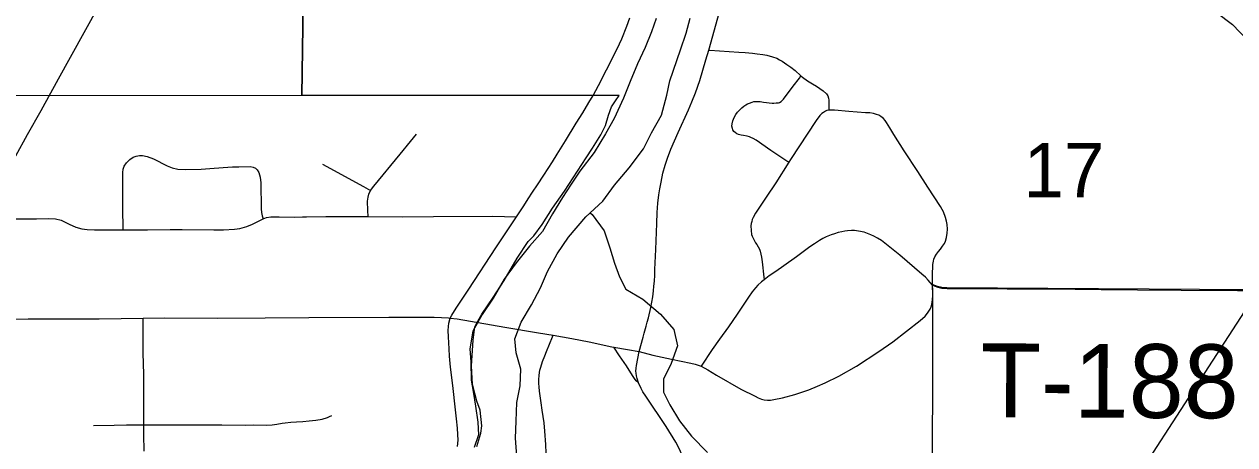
# Model space of a CAD drawing. Extents: x 0 to 34, y 0 to 22.
# Drawn here: x 4.151 to 4.6165, y 16.4424 to 16.6042 of the extents above; entities that cross this region are included whole.
import ezdxf

# ---------------------------------------------------------------- set-up
doc = ezdxf.new("R2010")
doc.units = 0
for name, color, linetype in [('GM_X_City_Street', 7, 'Continuous'), ('GM_X_Corporation', 7, 'Continuous'), ('GM_X_Major_River', 7, 'Continuous'), ('GM_X_Minor_River', 7, 'Continuous'), ('GM_X_Rail_Line', 7, 'Continuous'), ('GM_X_Section_Text', 7, 'Continuous'), ('GM_X_State_Route', 7, 'Continuous'), ('GM_X_Township_Road', 7, 'Continuous'), ('GM_X_Township_Road_Text', 7, 'Continuous')]:
    doc.layers.add(name, color=color, linetype=linetype)

msp = doc.modelspace()

# ---------------------------------------------------------------- linework, layer by layer
at = {"layer": 'GM_X_City_Street'}
for points in [[(4.31768, 16.44178), (4.31786, 16.44419), (4.3178, 16.44636), (4.31761, 16.44884), (4.31728, 16.45232), (4.31681, 16.45588), (4.31578, 16.46515), (4.31494, 16.47224), (4.31456, 16.47645), (4.31439, 16.47932), (4.31411, 16.48398), (4.31407, 16.48635), (4.31419, 16.48793), (4.31435, 16.48913), (4.31478, 16.49112), (4.31549, 16.49227), (4.31717, 16.495), (4.322, 16.50227), (4.33243, 16.51819), (4.34034, 16.53016), (4.34313, 16.53439), (4.34479, 16.537), (4.34649, 16.53959), (4.34837, 16.54244), (4.35077, 16.54608), (4.35412, 16.55131), (4.35591, 16.5542), (4.35909, 16.5594), (4.36331, 16.56621), (4.36578, 16.57013), (4.36818, 16.57412), (4.36973, 16.5768), (4.37181, 16.58061), (4.37497, 16.58665), (4.37898, 16.5947), (4.38078, 16.59862), (4.38278, 16.60347), (4.38391, 16.60667)], [(4.38744, 16.47824), (4.38899, 16.48386), (4.38941, 16.48534), (4.39014, 16.48802), (4.39051, 16.48953), (4.39101, 16.4913), (4.39193, 16.4952), (4.39272, 16.49935), (4.39305, 16.50157), (4.39313, 16.50338), (4.39338, 16.50535), (4.39347, 16.50765), (4.39355, 16.50982), (4.39387, 16.51756), (4.39421, 16.52751), (4.39444, 16.53183), (4.39469, 16.53537), (4.3951, 16.53858), (4.39543, 16.54088), (4.39592, 16.54351), (4.39658, 16.54688), (4.39748, 16.54993), (4.39839, 16.55272), (4.3997, 16.55618), (4.40242, 16.56251), (4.4064, 16.57129), (4.40776, 16.57435), (4.40913, 16.57786), (4.41076, 16.58254), (4.41195, 16.58652), (4.41317, 16.59056), (4.41422, 16.59427)], [(4.41422, 16.59427), (4.41468, 16.59424), (4.42576, 16.59344), (4.42824, 16.5933), (4.43103, 16.59304), (4.43289, 16.59287), (4.43506, 16.59257), (4.4366, 16.59229), (4.43874, 16.59171), (4.44036, 16.59112), (4.44144, 16.59058), (4.44248, 16.59003), (4.44425, 16.58876), (4.44579, 16.58767), (4.4474, 16.58642), (4.44968, 16.58431)], [(4.44498, 16.55109), (4.4442, 16.55159), (4.43817, 16.55565), (4.43242, 16.55955), (4.43131, 16.56022), (4.43044, 16.56062), (4.42985, 16.56084), (4.42904, 16.56109), (4.42765, 16.5614), (4.42671, 16.56155), (4.42568, 16.56182), (4.42497, 16.56211), (4.42438, 16.56251), (4.42391, 16.563), (4.42354, 16.56357), (4.42334, 16.56409), (4.42316, 16.56499), (4.4232, 16.56589), (4.42345, 16.56702), (4.42398, 16.56832), (4.42466, 16.56953), (4.42535, 16.57043), (4.426, 16.57118), (4.42696, 16.57205), (4.4277, 16.57267), (4.42851, 16.5732), (4.42919, 16.57358), (4.42988, 16.57391), (4.4309, 16.57429), (4.43162, 16.57444), (4.43239, 16.5745), (4.43317, 16.5745), (4.43401, 16.57444), (4.43534, 16.57426), (4.43647, 16.57411), (4.43749, 16.57398), (4.43865, 16.57387), (4.43932, 16.57385), (4.44022, 16.57392), (4.441, 16.57401), (4.44149, 16.57417), (4.44208, 16.57451), (4.44252, 16.57489), (4.44295, 16.57544), (4.44664, 16.58035), (4.44907, 16.58351), (4.44968, 16.58431)], [(4.44968, 16.58431), (4.45022, 16.58387), (4.45225, 16.58247), (4.4541, 16.58134), (4.45564, 16.58038), (4.45826, 16.57857), (4.45945, 16.57746), (4.46005, 16.57665), (4.46028, 16.57583), (4.4604, 16.57497), (4.46039, 16.57402), (4.46036, 16.57193), (4.46035, 16.5711)], [(4.46035, 16.5711), (4.4597, 16.57098), (4.45913, 16.57073), (4.45834, 16.57032), (4.45773, 16.56987), (4.45696, 16.56909), (4.45556, 16.56713), (4.44564, 16.55213), (4.44498, 16.55109)], [(4.50031, 16.50375), (4.50025, 16.50865), (4.50036, 16.51055), (4.50043, 16.51174), (4.50063, 16.51301), (4.5008, 16.51387), (4.50117, 16.51478), (4.50182, 16.51577), (4.50256, 16.51671), (4.50334, 16.5177), (4.50417, 16.51877), (4.50483, 16.51984), (4.50528, 16.52078), (4.50565, 16.52214), (4.50589, 16.52383), (4.50602, 16.52539), (4.50585, 16.5272), (4.50562, 16.52848), (4.50525, 16.52991), (4.50445, 16.53197), (4.50396, 16.53296), (4.5033, 16.53407), (4.49853, 16.54147), (4.49457, 16.5476), (4.48942, 16.55556), (4.48545, 16.56176), (4.48388, 16.56439), (4.48255, 16.56638), (4.48207, 16.56716), (4.48137, 16.56798), (4.4804, 16.56878), (4.47966, 16.5692), (4.4787, 16.56955), (4.47759, 16.56987), (4.47619, 16.57008), (4.47447, 16.57016), (4.4681, 16.57062), (4.46262, 16.5711), (4.46121, 16.57118), (4.46035, 16.5711)], [(4.28423, 16.5402), (4.28552, 16.54196), (4.29559, 16.55421), (4.2995, 16.55904), (4.3019, 16.56189)], [(4.18908, 16.52511), (4.18906, 16.52647), (4.18898, 16.53226), (4.18895, 16.54717), (4.18906, 16.5484), (4.1895, 16.54956), (4.19033, 16.55084), (4.19166, 16.55214), (4.19296, 16.55301), (4.19409, 16.5535), (4.1953, 16.55373), (4.19654, 16.5537), (4.19835, 16.55328), (4.20068, 16.55241), (4.20595, 16.54975), (4.20796, 16.54893), (4.21008, 16.54848), (4.21285, 16.54829), (4.21905, 16.54841), (4.22402, 16.54883), (4.22927, 16.5492), (4.2311, 16.54933), (4.23358, 16.54941), (4.23791, 16.54951), (4.23912, 16.54928), (4.23994, 16.54887), (4.24059, 16.54823), (4.24121, 16.54716), (4.24176, 16.54536), (4.24203, 16.5432), (4.24215, 16.53325), (4.24225, 16.53184), (4.24252, 16.53055), (4.24286, 16.52935)], [(4.26573, 16.55036), (4.28144, 16.54173), (4.28423, 16.5402)], [(4.44498, 16.55109), (4.44, 16.54322), (4.43632, 16.53767), (4.43377, 16.53381), (4.4322, 16.53146), (4.4313, 16.52989), (4.43093, 16.52903), (4.43076, 16.52834), (4.43056, 16.52755), (4.43047, 16.52659), (4.43049, 16.5248), (4.43068, 16.52333), (4.43089, 16.52261), (4.43151, 16.52134), (4.43225, 16.52015), (4.43274, 16.51941), (4.43328, 16.51859), (4.43373, 16.51772), (4.43397, 16.51686), (4.43426, 16.51579), (4.43447, 16.5146), (4.43472, 16.51283), (4.43538, 16.50695), (4.43549, 16.5059)], [(4.2833, 16.53026), (4.28321, 16.53257), (4.28308, 16.5361), (4.28322, 16.53765), (4.28353, 16.53885), (4.28423, 16.5402)], [(4.1446, 16.52931), (4.15577, 16.5294), (4.16048, 16.52951), (4.16302, 16.52929), (4.16524, 16.5288), (4.16834, 16.52729), (4.17086, 16.52619), (4.17318, 16.52554), (4.17527, 16.52522), (4.17802, 16.52509), (4.18908, 16.52511), (4.19011, 16.52512), (4.19848, 16.52517), (4.20716, 16.52521), (4.21181, 16.52518), (4.22389, 16.52514), (4.22759, 16.52517), (4.23189, 16.52532), (4.23398, 16.52563), (4.23661, 16.52634), (4.23886, 16.52724), (4.24286, 16.52935), (4.24421, 16.52981), (4.24585, 16.53005), (4.24901, 16.53012), (4.2549, 16.52999), (4.25799, 16.53005), (4.25955, 16.53009), (4.26699, 16.53024), (4.27632, 16.53023), (4.27911, 16.53023), (4.2833, 16.53026), (4.29629, 16.53014), (4.3084, 16.53027), (4.33108, 16.53042), (4.34034, 16.53016)], [(4.50031, 16.50375), (4.49863, 16.5058), (4.49763, 16.50688), (4.49623, 16.50809), (4.48775, 16.51537), (4.48193, 16.52003), (4.48065, 16.52094), (4.4791, 16.52194), (4.47772, 16.52267), (4.47662, 16.52322), (4.47534, 16.52374), (4.474, 16.52418), (4.47187, 16.52464), (4.47028, 16.5248), (4.46909, 16.52482), (4.46757, 16.52472), (4.46658, 16.52456), (4.46543, 16.52435), (4.46394, 16.52403), (4.46259, 16.52358), (4.46128, 16.52312), (4.45943, 16.52237), (4.45811, 16.52174), (4.45677, 16.52095), (4.4549, 16.51974), (4.4531, 16.51851), (4.44796, 16.51478), (4.44311, 16.51123), (4.43998, 16.50913), (4.43743, 16.50736), (4.43549, 16.5059)], [(4.43549, 16.5059), (4.43447, 16.50514), (4.43316, 16.50386), (4.43217, 16.50284), (4.43098, 16.50127), (4.42954, 16.49918), (4.42723, 16.49579), (4.42521, 16.49266), (4.42187, 16.4878), (4.41836, 16.48297), (4.41553, 16.47908), (4.41131, 16.47268)], [(4.41131, 16.47268), (4.41393, 16.47119), (4.41717, 16.46913), (4.4266, 16.46383), (4.43209, 16.46104), (4.43328, 16.46046), (4.43447, 16.45999), (4.43556, 16.45975), (4.43682, 16.45958), (4.43804, 16.45958), (4.4392, 16.45976), (4.44256, 16.4604), (4.44736, 16.46174), (4.44969, 16.46251), (4.45266, 16.46357), (4.45607, 16.46499), (4.45896, 16.46624), (4.46425, 16.46885), (4.471, 16.47269), (4.47961, 16.47828), (4.48497, 16.48201), (4.49555, 16.49021), (4.49742, 16.49186), (4.49841, 16.49304), (4.49891, 16.49383), (4.49937, 16.49464), (4.49973, 16.49546), (4.49999, 16.49639), (4.50013, 16.49726), (4.50028, 16.49823), (4.50041, 16.5), (4.50031, 16.50375)], [(4.11255, 16.49088), (4.12422, 16.49068), (4.15248, 16.49082), (4.1798, 16.4909), (4.1968, 16.49115)], [(4.19709, 16.4399), (4.19705, 16.44641), (4.19703, 16.45012), (4.19704, 16.45215), (4.19705, 16.45855), (4.19701, 16.46415), (4.19699, 16.46942), (4.19676, 16.47781), (4.19682, 16.48371), (4.19681, 16.48903), (4.1968, 16.49115)], [(4.1968, 16.49115), (4.20495, 16.49127), (4.22543, 16.49115), (4.24372, 16.49122), (4.26042, 16.49131), (4.29123, 16.49149), (4.3086, 16.49152), (4.31148, 16.4914), (4.31414, 16.4912), (4.31478, 16.49112)], [(4.31478, 16.49112), (4.31751, 16.4908), (4.33588, 16.48764), (4.34875, 16.48551), (4.35441, 16.48451)], [(4.35174, 16.43912), (4.35158, 16.44253), (4.35121, 16.44769), (4.35099, 16.45078), (4.35013, 16.45577), (4.34976, 16.45855), (4.34939, 16.46126), (4.34914, 16.46299), (4.34901, 16.46471), (4.34893, 16.46598), (4.34895, 16.46743), (4.34901, 16.46922), (4.34932, 16.47107), (4.34963, 16.47224), (4.35031, 16.47446), (4.35117, 16.47656), (4.35191, 16.47835), (4.35419, 16.48396), (4.35441, 16.48451)], [(4.35441, 16.48451), (4.36157, 16.48324), (4.36823, 16.48195), (4.37691, 16.48012), (4.37773, 16.47996)], [(4.37773, 16.47996), (4.38305, 16.47902), (4.38744, 16.47824)], [(4.38727, 16.46629), (4.38639, 16.46705), (4.38571, 16.46785), (4.3849, 16.46909), (4.38256, 16.47273), (4.37997, 16.4766), (4.37773, 16.47996)], [(4.38727, 16.46629), (4.38675, 16.46793), (4.38647, 16.46897), (4.38627, 16.46989), (4.38624, 16.47068), (4.38632, 16.47193), (4.38643, 16.47286), (4.38744, 16.47824)], [(4.38744, 16.47824), (4.39268, 16.47687), (4.39985, 16.47536), (4.40735, 16.47386), (4.409, 16.47346), (4.41131, 16.47268)], [(4.4054, 16.36954), (4.40567, 16.37964), (4.40607, 16.39475), (4.40636, 16.41465), (4.40625, 16.42644), (4.40607, 16.42857), (4.40595, 16.43043), (4.40559, 16.43262), (4.40532, 16.43405), (4.40484, 16.43567), (4.40449, 16.437), (4.40404, 16.43823), (4.40337, 16.43984), (4.40265, 16.44143), (4.40154, 16.4434), (4.3978, 16.44946), (4.39002, 16.46111), (4.38895, 16.46277), (4.38824, 16.46407), (4.38727, 16.46629)], [(4.17762, 16.44977), (4.18567, 16.44998), (4.19032, 16.45008), (4.19703, 16.45012), (4.20831, 16.45008), (4.21329, 16.45006), (4.22012, 16.45005), (4.22695, 16.45004), (4.23595, 16.44999), (4.23905, 16.45002), (4.24433, 16.44999), (4.24635, 16.45012), (4.24811, 16.45034), (4.25016, 16.4507), (4.25138, 16.45088), (4.25355, 16.45105), (4.25571, 16.45119), (4.25813, 16.45136), (4.26062, 16.45158), (4.26318, 16.45188), (4.26554, 16.45229), (4.26761, 16.45294), (4.26846, 16.45332), (4.26925, 16.45371)]]:
    msp.add_lwpolyline(points, dxfattribs=at)
at = {"layer": 'GM_X_Corporation'}
msp.add_lwpolyline([(4.26039, 16.75407), (4.25771, 16.57674), (3.71695, 16.57631), (3.72171, 16.75343)], close=True, dxfattribs=at)
for points in [[(4.32509, 16.4417), (4.32664, 16.44681), (4.32704, 16.44964), (4.32633, 16.45572), (4.32503, 16.45913), (4.32337, 16.46559), (4.32305, 16.47279), (4.32369, 16.48264), (4.3243, 16.48775), (4.32545, 16.49002), (4.32699, 16.49266), (4.3314, 16.49907), (4.33561, 16.50566), (4.34061, 16.51415), (4.34482, 16.52056), (4.34692, 16.52282), (4.35018, 16.52715), (4.35421, 16.53338), (4.3588, 16.53997), (4.36705, 16.55279), (4.36954, 16.55656), (4.3728, 16.56165), (4.37453, 16.56524), (4.3757, 16.56921), (4.37686, 16.57243), (4.37839, 16.57469), (4.37974, 16.57676), (4.25771, 16.57674), (4.26039, 16.75407)], [(4.62236, 16.50198), (4.50576, 16.50283), (4.5038, 16.50297), (4.5022, 16.50329), (4.5002, 16.50403), (4.50026, 16.50168), (4.49995, 16.31044), (4.49987, 16.28913), (4.49991, 16.26455), (4.49949, 16.23944), (4.49942, 16.21594), (4.49926, 16.20296), (4.49493, 16.07236), (4.49487, 16.07005), (4.50943, 16.07493), (4.50714, 16.00003), (4.53953, 15.99954), (4.55741, 15.99929), (4.55753, 16.0215), (4.65286, 16.0199)]]:
    msp.add_lwpolyline(points, dxfattribs=at)
at = {"layer": 'GM_X_Major_River'}
for points in [[(4.35591, 16.51589), (4.36031, 16.52231), (4.36698, 16.53006), (4.37346, 16.53609), (4.37805, 16.54233), (4.38358, 16.54894), (4.38912, 16.55632), (4.39219, 16.56237), (4.39602, 16.56918), (4.39815, 16.57695), (4.39932, 16.58245), (4.40337, 16.59439), (4.40549, 16.60083), (4.40704, 16.60652)], [(4.39398, 16.6064), (4.39224, 16.60129), (4.38974, 16.59523), (4.38686, 16.58898), (4.38398, 16.58216), (4.38147, 16.57572), (4.37783, 16.56796), (4.37457, 16.5621), (4.37017, 16.55491)], [(4.37017, 16.55491), (4.36463, 16.54773), (4.36138, 16.54262), (4.35794, 16.53752), (4.35411, 16.53127), (4.35028, 16.52446), (4.34532, 16.5188), (4.34017, 16.51237), (4.33559, 16.50613), (4.33137, 16.49875), (4.32717, 16.49251), (4.32353, 16.48608), (4.32235, 16.47925), (4.3227, 16.47432), (4.32284, 16.46729), (4.32376, 16.46216), (4.32449, 16.45722), (4.3254, 16.45114), (4.32574, 16.4462), (4.32401, 16.44128)], [(4.34046, 16.43795), (4.33994, 16.44498), (4.34017, 16.45143), (4.3404, 16.45864), (4.34177, 16.46509), (4.342, 16.47155), (4.34014, 16.47782), (4.33961, 16.48314), (4.34211, 16.48958), (4.34613, 16.4962), (4.34958, 16.50282), (4.35227, 16.50907), (4.35591, 16.51589)]]:
    msp.add_lwpolyline(points, dxfattribs=at)
at = {"layer": 'GM_X_Minor_River'}
for points in [[(4.60934, 16.60893), (4.61556, 16.60415), (4.62139, 16.59804)], [(4.36868, 16.53163), (4.36945, 16.53099), (4.37396, 16.5247), (4.37619, 16.51823), (4.37805, 16.51234), (4.37991, 16.50701), (4.38234, 16.50225), (4.38895, 16.49841), (4.39573, 16.49268), (4.40081, 16.48676), (4.40228, 16.48049), (4.39978, 16.47367), (4.3969, 16.46761), (4.39687, 16.46268), (4.3993, 16.45773), (4.40305, 16.45163), (4.40756, 16.44572), (4.41377, 16.43942)]]:
    msp.add_lwpolyline(points, dxfattribs=at)
at = {"layer": 'GM_X_Rail_Line'}
msp.add_lwpolyline([(4.15293, 16.05922), (4.17398, 16.05703), (4.20024, 16.0564), (4.23441, 16.05966), (4.26773, 16.06786), (4.29331, 16.07623), (4.3164, 16.08865), (4.34332, 16.10532), (4.36475, 16.12232), (4.38646, 16.14048), (4.40334, 16.15893), (4.41816, 16.18091), (4.48068, 16.27821), (4.62499, 16.50082), (4.83086, 16.81428), (4.95348, 17.00356)], dxfattribs=at)
at = {"layer": 'GM_X_State_Route'}
for points in [[(4.15749, 16.57098), (4.16425, 16.58322), (4.17937, 16.6105), (4.18885, 16.6276), (4.19694, 16.64221), (4.20149, 16.65038), (4.21297, 16.67098), (4.22005, 16.68378), (4.22806, 16.69822), (4.22908, 16.69991)], [(4.08055, 16.43308), (4.08909, 16.44896), (4.09083, 16.4522), (4.09419, 16.45794), (4.09536, 16.45993), (4.10431, 16.47638), (4.11077, 16.48775), (4.11255, 16.49088), (4.11282, 16.49135), (4.12247, 16.50851), (4.12736, 16.51719), (4.13145, 16.52446), (4.13414, 16.52926), (4.13512, 16.53102), (4.13977, 16.53933), (4.14417, 16.54721), (4.14776, 16.55364), (4.15235, 16.56175), (4.15749, 16.57098)]]:
    msp.add_lwpolyline(points, dxfattribs=at)
at = {"layer": 'GM_X_Township_Road'}
for points in [[(4.41422, 16.59427), (4.41773, 16.6067), (4.41915, 16.61174), (4.42367, 16.62757), (4.42671, 16.6386), (4.42904, 16.64703), (4.43402, 16.66598), (4.43835, 16.68283), (4.44079, 16.69248), (4.44283, 16.69936), (4.44405, 16.7029), (4.44572, 16.70693), (4.44648, 16.70869)], [(4.50031, 16.50375), (4.50231, 16.50301), (4.50391, 16.5027), (4.50587, 16.50255), (4.50913, 16.50247), (4.51687, 16.50247), (4.52895, 16.50242), (4.54278, 16.50235), (4.55509, 16.50229), (4.56517, 16.50218), (4.57905, 16.50204), (4.59583, 16.50185), (4.61754, 16.50171), (4.62247, 16.5017), (4.62538, 16.50174)]]:
    msp.add_lwpolyline(points, dxfattribs=at)

# ---------------------------------------------------------------- texts
at = {"layer": 'GM_X_Section_Text'}
msp.add_text('17', height=0.020928, rotation=0, dxfattribs=at).set_placement((4.53527, 16.53764))
at = {"layer": 'GM_X_Township_Road_Text'}
msp.add_text('T-188', height=0.028409, rotation=359.7232, dxfattribs=at).set_placement((4.5187, 16.45304))

doc.saveas('drawing.dxf')
